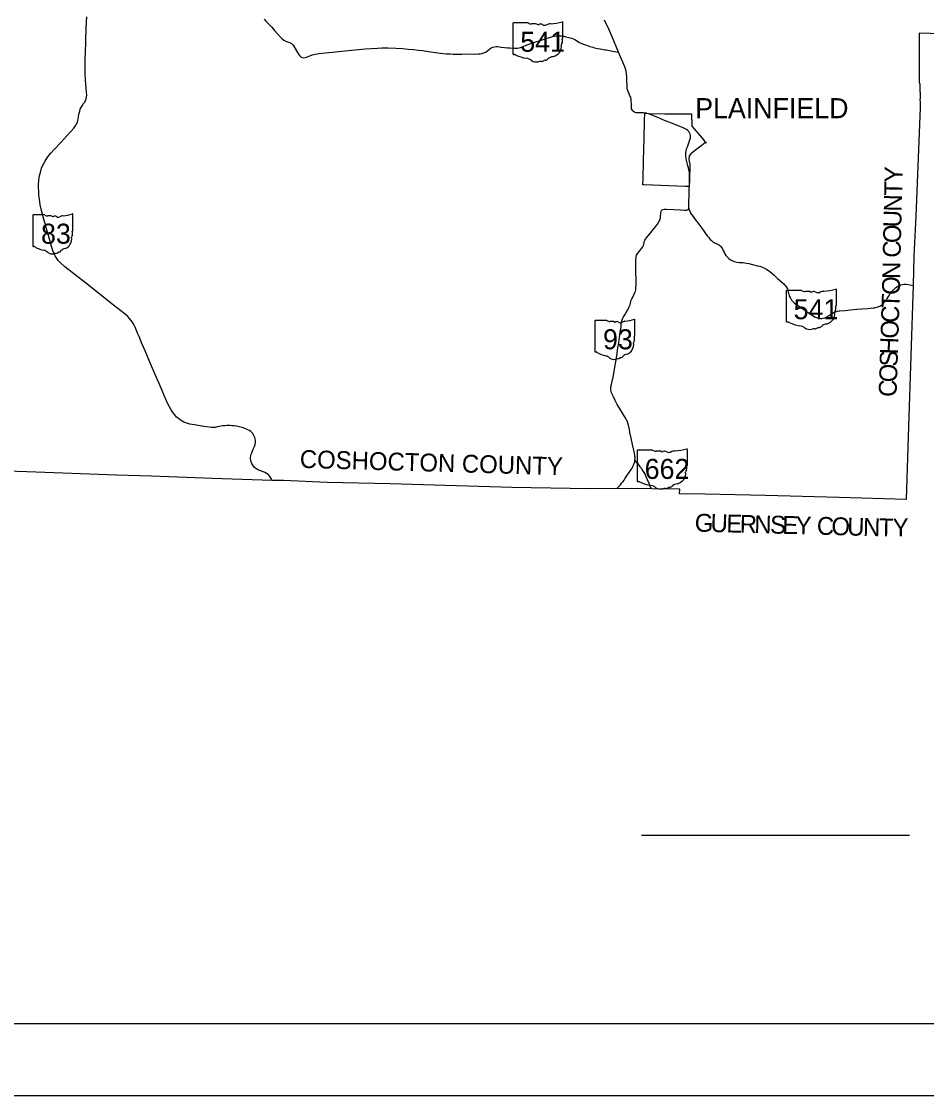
# Model space of a CAD drawing. Extents: x 1913970 to 2276415, y 78841 to 927181.
# Drawn here: x 2150744 to 2201350, y 751181 to 811241 of the extents above; entities that cross this region are included whole.
import ezdxf

# ---------------------------------------------------------------- set-up
doc = ezdxf.new("R2010")
doc.units = 0
for name, color, linetype in [('GM_X_Corporation', 7, 'Continuous'), ('GM_X_Corporation_Text', 7, 'Continuous'), ('GM_X_County', 7, 'Continuous'), ('GM_X_County_Text', 7, 'Continuous'), ('GM_X_State_Location', 7, 'Continuous'), ('GM_X_State_Route', 7, 'Continuous'), ('GM_X_State_Shield', 7, 'Continuous'), ('SH_Border', 7, 'Continuous'), ('SH_Cut_Line', 7, 'Continuous'), ('UT_P_Electric', 7, 'Continuous')]:
    doc.layers.add(name, color=color, linetype=linetype)

msp = doc.modelspace()

# ---------------------------------------------------------------- linework, layer by layer
at = {"layer": 'GM_X_Corporation'}
msp.add_lwpolyline([(2188202, 806076), (2188226, 805385), (2188802, 804717), (2188942, 804541), (2189054, 804450), (2188964, 804448), (2188196, 803855), (2188072, 803729), (2188061, 803514), (2188113, 803240), (2188099, 802359), (2188083, 802010), (2187853, 802017), (2185559, 802104), (2185485, 802109), (2185490, 802165), (2185498, 802416), (2185528, 803463), (2185557, 804719), (2185559, 804771), (2185568, 805116), (2185574, 805266), (2185576, 805326), (2185581, 805536), (2185589, 805879), (2185591, 805947), (2185596, 806107), (2185831, 806102), (2186692, 806078), (2186962, 806079), (2186976, 806079), (2187930, 806077), (2188038, 806076)], close=True, dxfattribs=at)
at = {"layer": 'GM_X_County'}
msp.add_lwpolyline([(2205381, 810448), (2200936, 810586), (2200946, 807855), (2200966, 807785), (2200976, 807730), (2200976, 807629), (2200975, 807541), (2200976, 807471), (2200980, 807397), (2200985, 807329), (2200988, 807267), (2200988, 807202), (2200988, 807107), (2200989, 807027), (2200986, 806939), (2200984, 806875), (2200988, 806732), (2200989, 806696), (2200991, 806637), (2200991, 806584), (2200992, 806538), (2200989, 806420), (2200752, 800346), (2200640, 798126), (2200607, 796487), (2200352, 788594), (2200213, 784515), (2196471, 784613), (2192356, 784732), (2188969, 784801), (2187543, 784833), (2187559, 785091), (2185988, 785114), (2184041, 785134), (2182507, 785112), (2178155, 785189), (2171358, 785391), (2167834, 785463), (2165393, 785569), (2164756, 785563), (2161402, 785685), (2158022, 785823), (2156064, 785864), (2151050, 786066), (2149915, 786091)], dxfattribs=at)
at = {"layer": 'GM_X_State_Route'}
for p, q in [((2184474, 808706), (2184130, 809527)), ((2186452, 805810), (2186370, 805844)), ((2186527, 805780), (2186452, 805810)), ((2186603, 805750), (2186527, 805780)), ((2186849, 805649), (2186603, 805750)), ((2187279, 805476), (2187180, 805513)), ((2184048, 792669), (2184079, 792888))]:
    msp.add_line(p, q, dxfattribs=at)
for points in [[(2164757, 785560), (2164733, 785632), (2164709, 785684), (2164671, 785748), (2164634, 785804), (2164592, 785857), (2164532, 785910), (2164454, 785966), (2164357, 786019), (2164216, 786074), (2164058, 786127), (2163939, 786180), (2163843, 786240), (2163746, 786326), (2163674, 786422), (2163616, 786530), (2163584, 786625), (2163565, 786704), (2163556, 786783), (2163559, 786862), (2163570, 786948), (2163593, 787037), (2163623, 787122), (2163700, 787319), (2163765, 787465), (2163808, 787581), (2163829, 787671), (2163834, 787752), (2163829, 787826), (2163814, 787909), (2163794, 787985), (2163763, 788060), (2163725, 788131), (2163676, 788200), (2163630, 788253), (2163563, 788312), (2163486, 788366), (2163407, 788409), (2163292, 788460), (2163203, 788495), (2163083, 788536), (2162924, 788577), (2162764, 788609), (2162635, 788629), (2162510, 788637), (2162418, 788640), (2162225, 788642), (2162109, 788633), (2161998, 788622), (2161889, 788603), (2161695, 788566), (2161566, 788543), (2161513, 788538), (2161370, 788534), (2161230, 788550), (2160944, 788594), (2160414, 788678), (2160167, 788721), (2160049, 788752), (2159937, 788789), (2159822, 788840), (2159729, 788888), (2159633, 788948), (2159515, 789032), (2159420, 789119), (2159314, 789238), (2159227, 789352), (2159138, 789486), (2159043, 789648), (2158955, 789815), (2158861, 790019), (2158724, 790332), (2158606, 790603), (2158441, 790998), (2158355, 791194), (2157985, 792060), (2157663, 792816), (2157482, 793240), (2157317, 793624), (2157235, 793814), (2157094, 794149), (2157039, 794262), (2156992, 794350), (2156927, 794450), (2156862, 794541), (2156786, 794633), (2156684, 794745), (2156536, 794875), (2156302, 795062), (2155724, 795516), (2154491, 796490), (2153587, 797203), (2153177, 797526), (2152905, 797764), (2152804, 797881), (2152727, 797987), (2152633, 798134), (2152567, 798256), (2152513, 798379), (2152470, 798497), (2152417, 798680), (2152325, 799012), (2152252, 799276), (2152149, 799653), (2152084, 799883), (2152022, 800107), (2151939, 800400), (2151847, 800746), (2151795, 800993), (2151765, 801161), (2151748, 801282), (2151733, 801423), (2151722, 801530), (2151708, 801778), (2151705, 801911), (2151700, 802105), (2151712, 802357), (2151731, 802497), (2151753, 802619), (2151780, 802736), (2151819, 802875), (2151873, 803034), (2151922, 803160), (2151988, 803299), (2152061, 803432), (2152178, 803612), (2152272, 803737), (2152389, 803879), (2152599, 804108), (2152944, 804482), (2153274, 804843), (2153526, 805109), (2153680, 805282), (2153751, 805383), (2153798, 805459), (2153869, 805630), (2153913, 805775), (2153941, 805935), (2153973, 806120), (2153999, 806227), (2154032, 806333), (2154075, 806429), (2154131, 806527), (2154220, 806645), (2154279, 806729), (2154323, 806814), (2154358, 806907), (2154383, 807013), (2154392, 807138), (2154383, 807286), (2154359, 807509), (2154321, 807969), (2154305, 808305), (2154300, 808575), (2154298, 808874), (2154308, 809236), (2154316, 809440), (2154341, 810180), (2154364, 810834), (2154383, 811230), (2154395, 811500)], [(2164317, 811364), (2164429, 811237), (2164570, 811097), (2164735, 810924), (2164896, 810740), (2165063, 810547), (2165231, 810358), (2165312, 810279), (2165408, 810202), (2165482, 810153), (2165572, 810115), (2165790, 810041), (2165846, 810009), (2165888, 809975), (2165938, 809914), (2166234, 809416), (2166292, 809331), (2166339, 809279), (2166388, 809239), (2166455, 809218), (2166528, 809213), (2166598, 809222), (2166686, 809248), (2166862, 809319), (2166996, 809370), (2167367, 809453), (2169964, 809711), (2170658, 809749), (2170886, 809765), (2171023, 809772), (2171250, 809770), (2171678, 809745), (2172045, 809721), (2172371, 809697), (2172640, 809673), (2172955, 809635), (2173162, 809611), (2173512, 809562), (2173888, 809508), (2174028, 809490), (2174173, 809474), (2174329, 809456), (2174505, 809437), (2174709, 809425), (2174884, 809420), (2175206, 809418), (2175370, 809420), (2175591, 809423), (2176064, 809421), (2176280, 809423), (2176393, 809431), (2176495, 809452), (2176581, 809479), (2176682, 809527), (2176777, 809588), (2176939, 809717), (2177013, 809763), (2177106, 809804), (2177190, 809830), (2177279, 809840), (2177373, 809836), (2177544, 809813), (2177754, 809785), (2177912, 809770), (2178055, 809763), (2178320, 809751), (2178484, 809747), (2178570, 809760), (2178656, 809786), (2178935, 809895), (2179176, 809988), (2179391, 810063), (2179684, 810161), (2180087, 810284), (2180460, 810401), (2180538, 810420), (2180639, 810434), (2180820, 810439), (2180940, 810432), (2181062, 810412), (2181176, 810390), (2181342, 810350), (2181499, 810308), (2181597, 810273), (2181685, 810232), (2181826, 810139), (2181916, 810085), (2182017, 810033), (2182161, 809979), (2182345, 809910), (2182526, 809844), (2182683, 809796), (2182794, 809767), (2182946, 809734), (2183109, 809706), (2183382, 809658), (2183440, 809648), (2183620, 809616), (2183891, 809567), (2184130, 809527)], [(2184130, 809527), (2183766, 810381), (2183599, 810770), (2183346, 811321)], [(2184692, 807267), (2184668, 807324), (2184639, 807415), (2184619, 807519), (2184610, 807647), (2184602, 807958), (2184594, 808142), (2184573, 808322), (2184548, 808458), (2184511, 808588), (2184474, 808706)], [(2184863, 806354), (2184857, 806389), (2184850, 806443), (2184847, 806599), (2184838, 806821), (2184828, 806908), (2184808, 806999), (2184769, 807092), (2184716, 807210), (2184692, 807267)], [(2185714, 806102), (2185699, 806107), (2185630, 806121), (2185533, 806133), (2185412, 806135), (2185211, 806132), (2185120, 806137), (2185068, 806148), (2185016, 806173), (2184961, 806210), (2184925, 806243), (2184885, 806302), (2184863, 806354)], [(2186012, 805993), (2185796, 806077), (2185714, 806102)], [(2186370, 805844), (2186131, 805943), (2186012, 805993)], [(2187180, 805513), (2187049, 805569), (2186849, 805649)], [(2187421, 805416), (2187284, 805474), (2187279, 805476)], [(2187935, 805197), (2187861, 805235), (2187741, 805287), (2187421, 805416)], [(2188145, 804740), (2188153, 804795), (2188152, 804858), (2188132, 804941), (2188097, 805019), (2188063, 805079), (2188004, 805143), (2187935, 805197)], [(2187933, 803455), (2187905, 803598), (2187891, 803710), (2187890, 803824), (2187898, 803923), (2187910, 803998), (2187936, 804115), (2187976, 804230), (2188037, 804396)], [(2188037, 804396), (2188138, 804673), (2188145, 804740)], [(2188037, 803048), (2188033, 803064), (2188005, 803166), (2187981, 803261), (2187960, 803338), (2187944, 803403), (2187933, 803455)], [(2188090, 802790), (2188077, 802869), (2188056, 802969), (2188037, 803048)], [(2188088, 802058), (2188089, 802105), (2188094, 802242), (2188099, 802518), (2188100, 802656), (2188094, 802769), (2188090, 802790)], [(2188060, 800796), (2188054, 800838), (2188054, 800936), (2188054, 800960), (2188055, 801010), (2188063, 801246), (2188070, 801441), (2188085, 801884), (2188088, 802058)], [(2184079, 792888), (2184111, 793089), (2184138, 793267), (2184208, 793724), (2184247, 793986), (2184254, 794031), (2184267, 794156), (2184282, 794321), (2184294, 794419), (2184312, 794500), (2184344, 794604), (2184384, 794684), (2184472, 794834), (2184557, 794970), (2184641, 795112), (2184713, 795243), (2184748, 795325), (2184772, 795395), (2184791, 795480), (2184816, 795580), (2184842, 795649), (2184875, 795727), (2184905, 795796), (2184988, 795957), (2185048, 796079), (2185072, 796156), (2185090, 796238), (2185100, 796337), (2185111, 796540), (2185114, 796703), (2185116, 796884), (2185103, 797125), (2185092, 797405), (2185088, 797522), (2185094, 797721), (2185099, 797884), (2185112, 798050), (2185121, 798116), (2185136, 798166), (2185165, 798228), (2185206, 798288), (2185299, 798397), (2185422, 798540), (2185489, 798644), (2185522, 798722), (2185541, 798786), (2185558, 798887), (2185572, 798949), (2185593, 799008), (2185628, 799075), (2185684, 799143), (2185762, 799229), (2185870, 799358), (2186005, 799535), (2186189, 799750), (2186301, 799900), (2186389, 800038), (2186415, 800089), (2186439, 800147), (2186454, 800203), (2186470, 800261), (2186478, 800337), (2186494, 800510), (2186504, 800588), (2186516, 800631), (2186538, 800669), (2186569, 800703), (2186613, 800728), (2186680, 800738), (2186805, 800738), (2187220, 800720), (2187583, 800704), (2187818, 800691), (2187946, 800693), (2187982, 800704), (2188016, 800727), (2188037, 800758), (2188060, 800796)], [(2188060, 800796), (2188067, 800744), (2188085, 800684), (2188107, 800632), (2188140, 800560), (2188176, 800500), (2188225, 800428), (2188296, 800328), (2188419, 800165), (2188618, 799901), (2188783, 799681), (2188914, 799504), (2188998, 799387), (2189093, 799257), (2189151, 799180), (2189207, 799105), (2189257, 799048), (2189301, 799006), (2189360, 798956), (2189428, 798908), (2189494, 798868), (2189632, 798807), (2189691, 798778), (2189743, 798747), (2189792, 798709), (2189844, 798662), (2189894, 798602), (2189941, 798526), (2189985, 798435), (2190027, 798342), (2190074, 798250), (2190133, 798160), (2190216, 798063), (2190303, 797984), (2190390, 797921), (2190457, 797883), (2190522, 797851), (2190597, 797819), (2190662, 797799), (2190752, 797780), (2190869, 797768), (2191001, 797766), (2191089, 797761), (2191195, 797746), (2191275, 797731), (2191421, 797698), (2191625, 797649), (2191900, 797582), (2192022, 797549), (2192132, 797516), (2192289, 797452), (2192396, 797391), (2192480, 797340), (2192572, 797272), (2192726, 797140), (2192823, 797054), (2192902, 796985), (2193025, 796876), (2193129, 796784), (2193284, 796645), (2193375, 796563), (2193415, 796523), (2193461, 796464), (2193503, 796405), (2193540, 796350), (2193572, 796283), (2193598, 796212), (2193621, 796109), (2193644, 795996), (2193663, 795923), (2193694, 795853), (2193739, 795760), (2193809, 795657), (2193861, 795592), (2193909, 795545), (2193975, 795489), (2194069, 795422), (2194117, 795388), (2194249, 795299), (2194552, 795090), (2194868, 794874), (2194949, 794818), (2195041, 794754), (2195117, 794713), (2195195, 794681), (2195261, 794661), (2195335, 794646), (2195418, 794639), (2195489, 794639), (2195564, 794648), (2195660, 794673), (2195725, 794698), (2195790, 794731), (2195830, 794757), (2195937, 794832), (2196030, 794895), (2196109, 794938), (2196194, 794979), (2196282, 795013), (2196374, 795039), (2196443, 795051), (2196511, 795061), (2196808, 795086), (2197095, 795109), (2197451, 795144), (2197730, 795168), (2198069, 795194), (2198362, 795219), (2198442, 795230), (2198504, 795245), (2198623, 795280), (2198734, 795330), (2198853, 795396), (2198923, 795452), (2198991, 795522), (2199054, 795597), (2199106, 795671), (2199151, 795745), (2199218, 795858), (2199297, 795990), (2199372, 796095), (2199442, 796181), (2199533, 796275), (2199633, 796361), (2199720, 796419), (2199797, 796465), (2199890, 796505), (2200008, 796535), (2200109, 796545), (2200217, 796544), (2200349, 796528), (2200506, 796504), (2200608, 796484)], [(2185051, 786832), (2185051, 786876), (2185047, 786942), (2185045, 786995), (2185027, 787099), (2184992, 787263), (2184918, 787587), (2184836, 787944), (2184768, 788262), (2184734, 788421), (2184681, 788675), (2184657, 788778), (2184633, 788864), (2184602, 788932), (2184541, 789044), (2184387, 789279), (2184180, 789620), (2184060, 789818), (2183946, 790045), (2183850, 790246), (2183744, 790483), (2183710, 790574), (2183693, 790648), (2183690, 790724), (2183697, 790804), (2183729, 790944), (2183792, 791212), (2183821, 791332), (2183848, 791470), (2183886, 791667), (2183930, 791908), (2183977, 792199), (2184048, 792669)], [(2184042, 785132), (2184127, 785222), (2184231, 785334), (2184302, 785417), (2184371, 785502), (2184440, 785592), (2184490, 785670), (2184559, 785772), (2184619, 785862), (2184683, 785956), (2184728, 786025), (2184767, 786080), (2184839, 786190), (2184883, 786265), (2184925, 786331), (2184948, 786384), (2184969, 786434), (2184989, 786486), (2185003, 786529), (2185018, 786583), (2185032, 786645), (2185045, 786733), (2185051, 786818), (2185051, 786832)], [(2185989, 785111), (2185968, 785136), (2185944, 785171), (2185920, 785208), (2185897, 785253), (2185833, 785402), (2185746, 785604), (2185671, 785777), (2185611, 785920), (2185565, 786021), (2185531, 786084), (2185497, 786136), (2185470, 786177), (2185418, 786243), (2185387, 786284), (2185341, 786339), (2185296, 786396), (2185219, 786495), (2185159, 786566), (2185112, 786624), (2185077, 786672), (2185066, 786688), (2185045, 786733)]]:
    msp.add_lwpolyline(points, dxfattribs=at)
at = {"layer": 'GM_X_State_Shield'}
for p, q in [((2178222, 811127), (2178222, 809426)), ((2179070, 811156), (2178249, 811156)), ((2181023, 810309), (2181023, 811199)), ((2181023, 810309), (2181023, 810309)), ((2151381, 800392), (2151381, 798691)), ((2152059, 800421), (2151403, 800421)), ((2153622, 799573), (2153622, 800463)), ((2153622, 799574), (2153622, 799573)), ((2193508, 796171), (2193508, 794470)), ((2194356, 796201), (2193536, 796201)), ((2196310, 795353), (2196310, 796243)), ((2196310, 795353), (2196310, 795353)), ((2182805, 794490), (2182805, 792789)), ((2183484, 794520), (2182827, 794520)), ((2185047, 793672), (2185047, 794562)), ((2185046, 793672), (2185047, 793672)), ((2185175, 787242), (2185175, 785541)), ((2186023, 787272), (2185202, 787272)), ((2187976, 786424), (2187976, 787314)), ((2187976, 786424), (2187976, 786424))]:
    msp.add_line(p, q, dxfattribs=at)
for centre, radius, start, end in [((2151407, 800396), 26, 98.1301, 188.1301), ((2152216, 800619), 252, 231.61951, 271.11188), ((2152299, 799466), 904, 80.48669, 94.98827), ((2152505, 800404), 72.7, 219.79206, 297.10237), ((2152611, 800208), 151, 54.46668, 119.14113), ((2152806, 800477), 182, 233.85621, 294.82819), ((2153127, 799902), 478, 97.34618, 120.76885), ((2152824, 802740), 2377, 275.84447, 288.90645), ((2153598, 800467), 25, 351.86209, 97.738), ((2153617, 799508), 38.6, 107.94398, 210.33697), ((2153371, 799396), 232, 340.03296, 23.64957), ((2153596, 799570), 26.7, 289.60381, 7.73413), ((2152957, 799088), 595, 292.30889, 8.98584), ((2153712, 799201), 169, 136.8065, 186.92959), ((2151407, 798687), 26.2, 171.95839, 258.30661), ((2151411, 798861), 200, 267.33899, 280.60386), ((2151452, 798593), 72.1, 29.74838, 93.27175), ((2152362, 800121), 1716, 240.41292, 257.1985), ((2151850, 797926), 537, 47.18416, 75.83597), ((2152431, 798584), 341, 230.70037, 286.29184), ((2152628, 797996), 280, 85.69512, 111.20995), ((2152653, 798457), 182, 268.77702, 315.54927), ((2152817, 798292), 51.1, 65.75173, 132.64842), ((2152795, 798526), 192, 282.87319, 323.27711), ((2153208, 798213), 326, 94.40312, 142.57675), ((2182831, 794494), 26, 98.1301, 188.1301), ((2183640, 794717), 252, 231.61951, 271.11188), ((2183724, 793565), 904, 80.48669, 94.98827), ((2183929, 794503), 72.7, 219.79206, 297.10237), ((2184036, 794306), 151, 54.46668, 119.14113), ((2184230, 794576), 182, 233.85621, 294.82819), ((2184551, 794000), 478, 97.34618, 120.76885), ((2184248, 796839), 2377, 275.84447, 288.90645), ((2185022, 794565), 25, 351.86209, 97.738), ((2185136, 793299), 169, 136.8065, 186.92959), ((2185041, 793607), 38.6, 107.94398, 210.33697), ((2184795, 793494), 232, 340.03296, 23.64957), ((2185020, 793668), 26.7, 289.60381, 7.73413), ((2184381, 793186), 595, 292.30889, 8.98584), ((2182831, 792785), 26.2, 171.95839, 258.30661), ((2182835, 792960), 200, 267.33899, 280.60386), ((2182876, 792691), 72.1, 29.74838, 93.27175), ((2183786, 794219), 1716, 240.41292, 257.1985), ((2183274, 792025), 537, 47.18416, 75.83597), ((2183855, 792683), 341, 230.70037, 286.29184), ((2184052, 792094), 280, 85.69512, 111.20995), ((2184077, 792555), 182, 268.77702, 315.54927), ((2184241, 792390), 51.1, 65.75173, 132.64842), ((2184220, 792624), 192, 282.87319, 323.27711), ((2184632, 792312), 326, 94.40312, 142.57675)]:
    msp.add_arc(centre, radius, start, end, dxfattribs=at)
for centre, major_axis, start_param, end_param in [((2178254, 811131), (32.5, 0), 1.712693, 3.28349), ((2179265, 811354), (315, 0), 4.042523, 4.731795), ((2179370, 810201), (1130, 0), 1.404758, 1.657858), ((2179626, 811140), (90.8, 0), 3.836095, 5.185415), ((2179759, 810943), (189, 0), 0.950623, 2.079405), ((2180003, 811213), (227, 0), 4.081561, 5.145723), ((2180404, 810637), (598, 0), 1.699011, 2.107814), ((2180025, 813476), (2971, 0), 4.814394, 5.042369), ((2180992, 811202), (31.2, 0), 6.141152, 7.989035), ((2181016, 810243), (48.3, 0), 1.883978, 3.671073), ((2180709, 810131), (290, 0), 5.934695, 6.695948), ((2180990, 810305), (33.4, 0), 5.05454, 6.418171), ((2180192, 809823), (743, 0), 5.101752, 6.440018), ((2181135, 809936), (211, 0), 2.387724, 3.262537), ((2178254, 809422), (32.7, 0), 3.00124, 4.508301), ((2178259, 809596), (250, 0), 4.665946, 4.897461), ((2178310, 809328), (90.1, 0), 0.519207, 1.627899), ((2179448, 810856), (2146, 0), 4.195997, 4.488961), ((2178808, 808662), (671, 0), 0.823519, 1.323587), ((2179534, 809319), (426, 0), 4.026481, 4.996735), ((2179780, 808731), (350, 0), 1.495662, 1.94098), ((2179811, 809192), (227, 0), 4.691044, 5.507374), ((2180017, 809027), (63.9, 0), 1.147584, 2.315152), ((2179989, 809261), (240, 0), 4.937069, 5.64225), ((2180505, 808948), (407, 0), 1.647645, 2.488434), ((2193540, 796175), (32.5, 0), 1.712693, 3.28349), ((2194552, 796398), (315, 0), 4.042523, 4.731795), ((2194656, 795246), (1130, 0), 1.404758, 1.657858), ((2194913, 796184), (90.8, 0), 3.836095, 5.185415), ((2195046, 795987), (189, 0), 0.950623, 2.079405), ((2195290, 796257), (227, 0), 4.081561, 5.145723), ((2195691, 795681), (598, 0), 1.699011, 2.107814), ((2195312, 798520), (2971, 0), 4.814394, 5.042369), ((2196279, 796247), (31.2, 0), 6.141152, 7.989035), ((2196303, 795288), (48.3, 0), 1.883978, 3.671073), ((2195996, 795175), (290, 0), 5.934695, 6.695948), ((2196277, 795349), (33.4, 0), 5.05454, 6.418171), ((2195479, 794867), (743, 0), 5.101752, 6.440018), ((2196422, 794980), (211, 0), 2.387724, 3.262537), ((2193541, 794466), (32.7, 0), 3.00124, 4.508301), ((2193546, 794641), (250, 0), 4.665946, 4.897461), ((2193597, 794372), (90.1, 0), 0.519207, 1.627899), ((2194734, 795900), (2146, 0), 4.195997, 4.488961), ((2194095, 793706), (671, 0), 0.823519, 1.323587), ((2194821, 794364), (426, 0), 4.026481, 4.996735), ((2195067, 793775), (350, 0), 1.495662, 1.94098), ((2195098, 794236), (227, 0), 4.691044, 5.507374), ((2195303, 794071), (63.9, 0), 1.147584, 2.315152), ((2195276, 794305), (240, 0), 4.937069, 5.64225), ((2195792, 793993), (407, 0), 1.647645, 2.488434), ((2185207, 787246), (32.5, 0), 1.712693, 3.28349), ((2186218, 787469), (315, 0), 4.042523, 4.731795), ((2186322, 786317), (1130, 0), 1.404758, 1.657858), ((2186579, 787255), (90.8, 0), 3.836095, 5.185415), ((2186712, 787058), (189, 0), 0.950623, 2.079405), ((2186956, 787328), (227, 0), 4.081561, 5.145723), ((2187357, 786752), (598, 0), 1.699011, 2.107814), ((2186978, 789591), (2971, 0), 4.814394, 5.042369), ((2187945, 787318), (31.2, 0), 6.141152, 7.989035), ((2187969, 786359), (48.3, 0), 1.883978, 3.671073), ((2187662, 786246), (290, 0), 5.934695, 6.695948), ((2187943, 786421), (33.4, 0), 5.05454, 6.418171), ((2187145, 785938), (743, 0), 5.101752, 6.440018), ((2188088, 786052), (211, 0), 2.387724, 3.262537), ((2185207, 785538), (32.7, 0), 3.00124, 4.508301), ((2185212, 785712), (250, 0), 4.665946, 4.897461), ((2185263, 785443), (90.1, 0), 0.519207, 1.627899), ((2186401, 786972), (2146, 0), 4.195997, 4.488961), ((2185761, 784777), (671, 0), 0.823519, 1.323587), ((2186487, 785435), (426, 0), 4.026481, 4.996735), ((2186733, 784847), (350, 0), 1.495662, 1.94098), ((2186764, 785307), (227, 0), 4.691044, 5.507374), ((2186970, 785143), (63.9, 0), 1.147584, 2.315152), ((2186942, 785376), (240, 0), 4.937069, 5.64225), ((2187458, 785064), (407, 0), 1.647645, 2.488434)]:
    msp.add_ellipse(centre, major_axis=major_axis, ratio=0.8, start_param=start_param, end_param=end_param, dxfattribs=at)
at = {"layer": 'SH_Border'}
msp.add_lwpolyline([(2016415, 923181), (2272415, 923181), (2272415, 755181), (2016415, 755181)], close=True, dxfattribs=at)
at = {"layer": 'SH_Cut_Line'}
msp.add_lwpolyline([(2004415, 751181), (2276415, 751181), (2276415, 927181), (2004415, 927181)], close=True, dxfattribs=at)
at = {"layer": 'UT_P_Electric'}
msp.add_line((2185405, 765741), (2200405, 765741), dxfattribs=at)

# ---------------------------------------------------------------- texts
at = {"layer": 'GM_X_Corporation_Text'}
msp.add_text('PLAINFIELD', height=1120, rotation=0.00001, dxfattribs=at).set_placement((2188416, 805833))
at = {"layer": 'GM_X_County_Text'}
for s, rotation, p in [('Y', 88.63575, (2199998, 802228)), ('T', 88.63575, (2199980, 801482)), ('N', 88.63727, (2199959, 800599)), ('U', 88.63684, (2199938, 799717)), ('O', 88.64992, (2199918, 798835)), ('C', 88.73764, (2199900, 798020)), ('N', 88.96217, (2199878, 796833)), ('O', 88.46902, (2199854, 795941)), ('T', 88.21262, (2199831, 795190)), ('C', 88.16164, (2199804, 794374)), ('O', 88.15834, (2199776, 793492)), ('H', 88.15937, (2199748, 792610)), ('S', 88.15904, (2199726, 791931)), ('O', 88.15939, (2199698, 791048)), ('C', 88.15938, (2199671, 790234)), ('COSHOCTON COUNTY', 358.37379, (2166297, 786281)), ('G', 358.54165, (2188380, 782718)), ('U', 358.54223, (2189264, 782696)), ('E', 358.54188, (2190148, 782673)), ('R', 358.54156, (2190896, 782654)), ('N', 358.54273, (2191710, 782633)), ('S', 358.54084, (2192594, 782611)), ('E', 358.54233, (2193271, 782594)), ('Y', 358.54165, (2194019, 782575)), ('C', 358.54134, (2195207, 782544)), ('O', 358.54145, (2196021, 782524)), ('U', 358.54205, (2196905, 782501)), ('N', 358.54464, (2197789, 782479)), ('T', 358.7696, (2198677, 782456)), ('Y', 1.32265, (2199474, 782440))]:
    msp.add_text(s, height=1000, rotation=rotation, dxfattribs=at).set_placement(p)
at = {"layer": 'GM_X_State_Location'}
for s, p in [('541', (2179338, 809972)), ('541', (2194548, 794691)), ('93', (2183949, 793459)), ('83', (2158605, 789838)), ('662', (2185242, 785772))]:
    msp.add_text(s, height=1, rotation=0.00001, dxfattribs=at).set_placement(p)
for s, p in [('s', (2179691, 810045)), ('r', (2179691, 810045)), ('s', (2194902, 794764)), ('r', (2194901, 794764)), ('s', (2184201, 793532)), ('r', (2184201, 793532)), ('s', (2158857, 789911)), ('r', (2158857, 789911)), ('s', (2185596, 785845)), ('r', (2185595, 785845))]:
    msp.add_text(s, height=1, dxfattribs=at).set_placement(p)
at = {"layer": 'GM_X_State_Shield'}
for s, p in [('541', (2178635, 809546)), ('83', (2151837, 798811)), ('541', (2193921, 794590)), ('93', (2183261, 792909)), ('662', (2185591, 785661))]:
    msp.add_text(s, height=1120.7, dxfattribs=at).set_placement(p)

doc.saveas('drawing.dxf')
